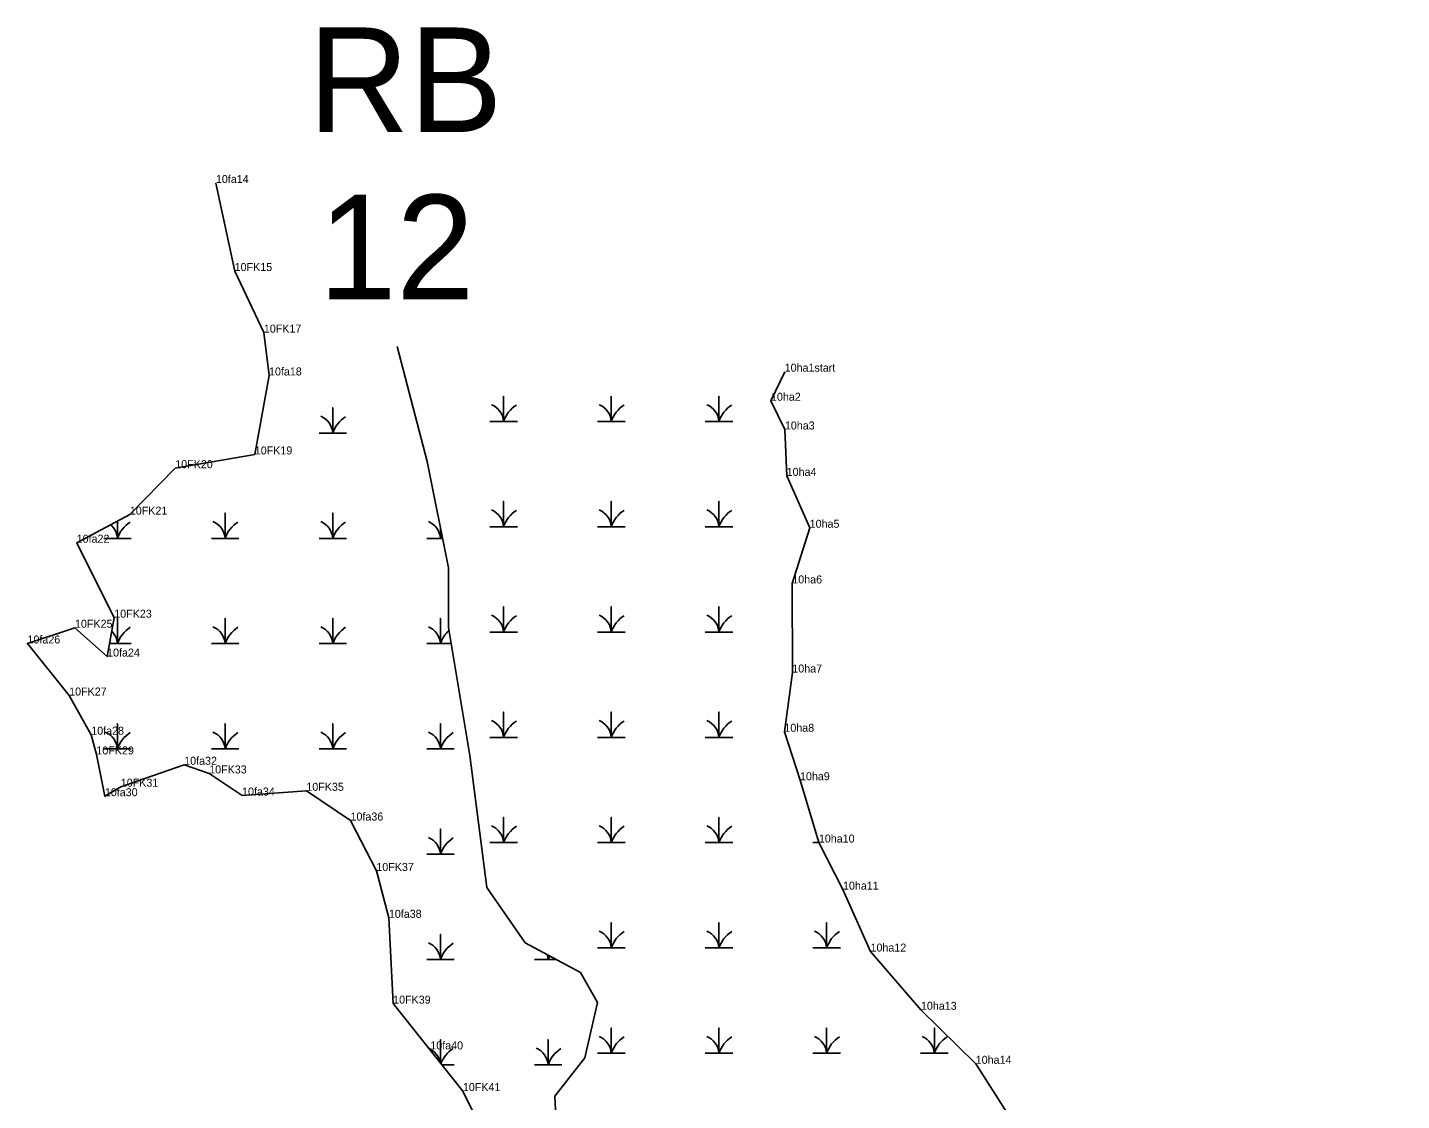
# Model space of a CAD drawing. Extents: x 2072529 to 2268796, y 436423 to 470397.
# Drawn here: x 2218305 to 2219163, y 449933 to 450603 of the extents above; entities that cross this region are included whole.
import ezdxf

# ---------------------------------------------------------------- set-up
doc = ezdxf.new("R2010")
doc.units = 0
for name, color, linetype in [('Default', 7, 'Continuous'), ('Exist Environmental Wetland Boundary', 7, 'Continuous'), ('Exist Environmental Wetland Boundary Cogo Comment', 7, 'Continuous'), ('Exist Environmental Wetland Boundary Cogo Point CELL', 7, 'Continuous'), ('Exist Hydro Jurisdictional Stream or Body of Water NEU Mitigable', 7, 'Continuous'), ('Exist Hydro Swamp or Marsh', 7, 'Continuous')]:
    doc.layers.add(name, color=color, linetype=linetype)

msp = doc.modelspace()

# ---------------------------------------------------------------- linework, layer by layer
at = {"layer": 'Exist Environmental Wetland Boundary'}
for points in [[(2218422.34, 450506.28), (2218434.05, 450451.3), (2218452.27, 450412.81), (2218455.5, 450386.02), (2218446.62, 450336.67), (2218396.94, 450328.09), (2218368.56, 450299.07), (2218335.38, 450281.52), (2218358.81, 450234.67), (2218354.37, 450210.38), (2218334.31, 450228.39), (2218304.63, 450218.55), (2218330.66, 450186.04), (2218344.46, 450161.54), (2218347.68, 450149.22), (2218352.97, 450123.12), (2218362.92, 450129.06), (2218402.51, 450142.76), (2218418.13, 450137.36), (2218438.68, 450123.54), (2218478.82, 450126.51), (2218506.4, 450107.92), (2218522.54, 450076.41), (2218530.37, 450047.14), (2218533.02, 449993.5), (2218576.58, 449938.89), (2218588.8, 449913.82)], [(2218777.6, 450388.4), (2218769.04, 450370.22), (2218777.71, 450352.27), (2218778.84, 450323.3), (2218793.2, 450290.87), (2218782.35, 450256.07), (2218782.37, 450200.42), (2218777.41, 450163.4), (2218787.16, 450133.1), (2218798.94, 450094.18), (2218814, 450064.74), (2218831.2, 450026.03), (2218862.69, 449989.66), (2218896.91, 449955.91), (2218918.55, 449921.84)]]:
    msp.add_lwpolyline(points, dxfattribs=at)
at = {"layer": 'Exist Environmental Wetland Boundary Cogo Point CELL'}
for p, q in [((2218422.34, 450506.28), (2218422.34, 450506.28)), ((2218434.05, 450451.3), (2218434.05, 450451.3)), ((2218434.05, 450451.3), (2218434.05, 450451.3)), ((2218452.27, 450412.81), (2218452.27, 450412.81)), ((2218452.27, 450412.81), (2218452.27, 450412.81)), ((2218455.5, 450386.02), (2218455.5, 450386.02)), ((2218777.6, 450388.4), (2218777.6, 450388.4)), ((2218769.04, 450370.22), (2218769.04, 450370.22)), ((2218769.04, 450370.22), (2218769.04, 450370.22)), ((2218777.71, 450352.27), (2218777.71, 450352.27)), ((2218446.62, 450336.67), (2218446.62, 450336.67)), ((2218446.62, 450336.67), (2218446.62, 450336.67)), ((2218396.94, 450328.09), (2218396.94, 450328.09)), ((2218396.94, 450328.09), (2218396.94, 450328.09)), ((2218778.84, 450323.3), (2218778.84, 450323.3)), ((2218778.84, 450323.3), (2218778.84, 450323.3)), ((2218368.56, 450299.07), (2218368.56, 450299.07)), ((2218368.56, 450299.07), (2218368.56, 450299.07)), ((2218793.2, 450290.87), (2218793.2, 450290.87)), ((2218335.38, 450281.52), (2218335.38, 450281.52)), ((2218782.35, 450256.07), (2218782.35, 450256.07)), ((2218782.35, 450256.07), (2218782.35, 450256.07)), ((2218358.81, 450234.67), (2218358.81, 450234.67)), ((2218358.81, 450234.67), (2218358.81, 450234.67)), ((2218334.31, 450228.39), (2218334.31, 450228.39)), ((2218334.31, 450228.39), (2218334.31, 450228.39)), ((2218304.63, 450218.55), (2218304.63, 450218.55)), ((2218354.37, 450210.38), (2218354.37, 450210.38)), ((2218782.37, 450200.42), (2218782.37, 450200.42)), ((2218330.66, 450186.04), (2218330.66, 450186.04)), ((2218330.66, 450186.04), (2218330.66, 450186.04)), ((2218344.46, 450161.54), (2218344.46, 450161.54)), ((2218777.41, 450163.4), (2218777.41, 450163.4)), ((2218777.41, 450163.4), (2218777.41, 450163.4)), ((2218347.68, 450149.22), (2218347.68, 450149.22)), ((2218347.68, 450149.22), (2218347.68, 450149.22)), ((2218402.51, 450142.76), (2218402.51, 450142.76)), ((2218418.13, 450137.36), (2218418.13, 450137.36)), ((2218418.13, 450137.36), (2218418.13, 450137.36)), ((2218362.92, 450129.06), (2218362.92, 450129.06)), ((2218362.92, 450129.06), (2218362.92, 450129.06)), ((2218478.82, 450126.51), (2218478.82, 450126.51)), ((2218478.82, 450126.51), (2218478.82, 450126.51)), ((2218787.16, 450133.1), (2218787.16, 450133.1)), ((2218352.97, 450123.12), (2218352.97, 450123.12)), ((2218438.68, 450123.54), (2218438.68, 450123.54)), ((2218506.4, 450107.92), (2218506.4, 450107.92)), ((2218798.94, 450094.18), (2218798.94, 450094.18)), ((2218798.94, 450094.18), (2218798.94, 450094.18)), ((2218522.54, 450076.41), (2218522.54, 450076.41)), ((2218522.54, 450076.41), (2218522.54, 450076.41)), ((2218814, 450064.74), (2218814, 450064.74)), ((2218530.37, 450047.14), (2218530.37, 450047.14)), ((2218831.2, 450026.03), (2218831.2, 450026.03)), ((2218831.2, 450026.03), (2218831.2, 450026.03)), ((2218533.02, 449993.5), (2218533.02, 449993.5)), ((2218533.02, 449993.5), (2218533.02, 449993.5)), ((2218862.69, 449989.66), (2218862.69, 449989.66)), ((2218556.25, 449964.92), (2218556.25, 449964.92)), ((2218896.91, 449955.91), (2218896.91, 449955.91)), ((2218896.91, 449955.91), (2218896.91, 449955.91)), ((2218576.58, 449938.89), (2218576.58, 449938.89)), ((2218576.58, 449938.89), (2218576.58, 449938.89))]:
    msp.add_line(p, q, dxfattribs=at)
at = {"layer": 'Exist Hydro Jurisdictional Stream or Body of Water NEU Mitigable'}
msp.add_lwpolyline([(2218535.63, 450404.2), (2218554.25, 450332.33), (2218567.55, 450265.78), (2218567.55, 450228.51), (2218580.85, 450148.65), (2218591.49, 450066.12), (2218615.44, 450031.52), (2218650.02, 450012.88), (2218660.66, 449994.25), (2218652.68, 449959.64), (2218634.06, 449935.68), (2218636.72, 449879.78), (2218647.36, 449829.2), (2218711.2, 449786.61), (2218727.16, 449736.03), (2218769.73, 449597.6), (2218825.59, 449536.38), (2218892.1, 449475.15), (2218953.28, 449435.22), (2219051.71, 449381.98), (2219115.55, 449339.39), (2219162.87, 449300.4)], dxfattribs=at)
at = {"layer": 'Exist Hydro Swamp or Marsh'}
for points in [[(2218593.46, 450357.3), (2218602.06, 450357.3), (2218602.06, 450373.08), (2218602.06, 450357.3), (2218610.66, 450357.3)], [(2218660.71, 450357.3), (2218669.31, 450357.3), (2218669.31, 450373.08), (2218669.31, 450357.3), (2218677.91, 450357.3)], [(2218727.96, 450357.3), (2218736.56, 450357.3), (2218736.56, 450373.08), (2218736.56, 450357.3), (2218745.16, 450357.3)], [(2218486.73, 450350.05), (2218495.33, 450350.05), (2218495.33, 450365.83), (2218495.33, 450350.05), (2218503.93, 450350.05)], [(2218593.46, 450291.5), (2218602.06, 450291.5), (2218602.06, 450307.28), (2218602.06, 450291.5), (2218610.66, 450291.5)], [(2218660.71, 450291.5), (2218669.31, 450291.5), (2218669.31, 450307.28), (2218669.31, 450291.5), (2218677.91, 450291.5)], [(2218727.96, 450291.5), (2218736.56, 450291.5), (2218736.56, 450307.28), (2218736.56, 450291.5), (2218745.16, 450291.5)], [(2218419.48, 450284.25), (2218428.08, 450284.25), (2218428.08, 450300.03), (2218428.08, 450284.25), (2218436.68, 450284.25)], [(2218486.73, 450284.25), (2218495.33, 450284.25), (2218495.33, 450300.03), (2218495.33, 450284.25), (2218503.93, 450284.25)], [(2218352.23, 450284.25), (2218360.83, 450284.25), (2218360.83, 450294.97)], [(2218360.83, 450294.97), (2218360.83, 450284.25), (2218369.43, 450284.25)], [(2218553.98, 450284.25), (2218562.58, 450284.25), (2218562.58, 450290.67)], [(2218562.58, 450290.67), (2218562.58, 450284.25), (2218563.86, 450284.25)], [(2218593.46, 450225.7), (2218602.06, 450225.7), (2218602.06, 450241.48), (2218602.06, 450225.7), (2218610.66, 450225.7)], [(2218660.71, 450225.7), (2218669.31, 450225.7), (2218669.31, 450241.48), (2218669.31, 450225.7), (2218677.91, 450225.7)], [(2218727.96, 450225.7), (2218736.56, 450225.7), (2218736.56, 450241.48), (2218736.56, 450225.7), (2218745.16, 450225.7)], [(2218355.85, 450218.45), (2218360.83, 450218.45), (2218360.83, 450234.23), (2218360.83, 450218.45), (2218369.43, 450218.45)], [(2218419.48, 450218.45), (2218428.08, 450218.45), (2218428.08, 450234.23), (2218428.08, 450218.45), (2218436.68, 450218.45)], [(2218486.73, 450218.45), (2218495.33, 450218.45), (2218495.33, 450234.23), (2218495.33, 450218.45), (2218503.93, 450218.45)], [(2218553.98, 450218.45), (2218562.58, 450218.45), (2218562.58, 450234.23), (2218562.58, 450218.45), (2218569.23, 450218.45)], [(2218593.46, 450159.9), (2218602.06, 450159.9), (2218602.06, 450175.68), (2218602.06, 450159.9), (2218610.66, 450159.9)], [(2218660.71, 450159.9), (2218669.31, 450159.9), (2218669.31, 450175.68), (2218669.31, 450159.9), (2218677.91, 450159.9)], [(2218727.96, 450159.9), (2218736.56, 450159.9), (2218736.56, 450175.68), (2218736.56, 450159.9), (2218745.16, 450159.9)], [(2218352.23, 450152.65), (2218360.83, 450152.65), (2218360.83, 450168.43), (2218360.83, 450152.65), (2218369.43, 450152.65)], [(2218419.48, 450152.65), (2218428.08, 450152.65), (2218428.08, 450168.43), (2218428.08, 450152.65), (2218436.68, 450152.65)], [(2218486.73, 450152.65), (2218495.33, 450152.65), (2218495.33, 450168.43), (2218495.33, 450152.65), (2218503.93, 450152.65)], [(2218553.98, 450152.65), (2218562.58, 450152.65), (2218562.58, 450168.43), (2218562.58, 450152.65), (2218571.18, 450152.65)], [(2218593.46, 450094.1), (2218602.06, 450094.1), (2218602.06, 450109.88), (2218602.06, 450094.1), (2218610.66, 450094.1)], [(2218660.71, 450094.1), (2218669.31, 450094.1), (2218669.31, 450109.88), (2218669.31, 450094.1), (2218677.91, 450094.1)], [(2218727.96, 450094.1), (2218736.56, 450094.1), (2218736.56, 450109.88), (2218736.56, 450094.1), (2218745.16, 450094.1)], [(2218553.98, 450086.85), (2218562.58, 450086.85), (2218562.58, 450102.63), (2218562.58, 450086.85), (2218571.18, 450086.85)], [(2218795.21, 450094.1), (2218798.98, 450094.1)], [(2218660.71, 450028.3), (2218669.31, 450028.3), (2218669.31, 450044.08), (2218669.31, 450028.3), (2218677.91, 450028.3)], [(2218727.96, 450028.3), (2218736.56, 450028.3), (2218736.56, 450044.08), (2218736.56, 450028.3), (2218745.16, 450028.3)], [(2218795.21, 450028.3), (2218803.81, 450028.3), (2218803.81, 450044.08), (2218803.81, 450028.3), (2218812.41, 450028.3)], [(2218553.98, 450021.05), (2218562.58, 450021.05), (2218562.58, 450036.83), (2218562.58, 450021.05), (2218571.18, 450021.05)], [(2218621.23, 450021.05), (2218629.83, 450021.05), (2218629.83, 450023.76)], [(2218629.83, 450023.76), (2218629.83, 450021.05), (2218634.86, 450021.05)], [(2218660.71, 449962.5), (2218669.31, 449962.5), (2218669.31, 449978.28), (2218669.31, 449962.5), (2218677.91, 449962.5)], [(2218727.96, 449962.5), (2218736.56, 449962.5), (2218736.56, 449978.28), (2218736.56, 449962.5), (2218745.16, 449962.5)], [(2218795.21, 449962.5), (2218803.81, 449962.5), (2218803.81, 449978.28), (2218803.81, 449962.5), (2218812.41, 449962.5)], [(2218862.46, 449962.5), (2218871.06, 449962.5), (2218871.06, 449978.28), (2218871.06, 449962.5), (2218879.66, 449962.5)], [(2218562.58, 449956.44), (2218562.58, 449971.03), (2218562.58, 449956.44)], [(2218621.23, 449955.25), (2218629.83, 449955.25), (2218629.83, 449971.03), (2218629.83, 449955.25), (2218638.43, 449955.25)], [(2218563.53, 449955.25), (2218571.18, 449955.25)]]:
    msp.add_lwpolyline(points, dxfattribs=at)
for centre, radius, start, end in [((2218589.79, 450356.41), 12.3, 4.14034, 67.53497), ((2218620.3, 450351.24), 19.22, 122.12745, 161.62219), ((2218657.04, 450356.41), 12.3, 4.14034, 67.53497), ((2218687.55, 450351.24), 19.22, 122.12745, 161.62219), ((2218724.29, 450356.41), 12.3, 4.14034, 67.53497), ((2218754.8, 450351.24), 19.22, 122.12745, 161.62219), ((2218483.06, 450349.16), 12.3, 4.14034, 67.53497), ((2218513.57, 450343.99), 19.22, 122.12745, 161.62219), ((2218589.79, 450290.61), 12.3, 4.14034, 67.53497), ((2218620.3, 450285.44), 19.22, 122.12745, 161.62219), ((2218657.04, 450290.61), 12.3, 4.14034, 67.53497), ((2218687.55, 450285.44), 19.22, 122.12745, 161.62219), ((2218724.29, 450290.61), 12.3, 4.14034, 67.53497), ((2218754.8, 450285.44), 19.22, 122.12745, 161.62219), ((2218348.56, 450283.36), 12.3, 4.14034, 49.48775), ((2218379.07, 450278.19), 19.22, 122.12745, 161.62219), ((2218415.81, 450283.36), 12.3, 4.14034, 67.53497), ((2218446.32, 450278.19), 19.22, 122.12745, 161.62219), ((2218483.06, 450283.36), 12.3, 4.14034, 67.53497), ((2218513.57, 450278.19), 19.22, 122.12745, 161.62219), ((2218550.31, 450283.36), 12.3, 4.14034, 67.53497), ((2218580.82, 450278.19), 19.22, 154.75438, 161.62219), ((2218589.79, 450224.81), 12.3, 4.14034, 67.53497), ((2218620.3, 450219.64), 19.22, 122.12745, 161.62219), ((2218657.04, 450224.81), 12.3, 4.14034, 67.53497), ((2218687.55, 450219.64), 19.22, 122.12745, 161.62219), ((2218724.29, 450224.81), 12.3, 4.14034, 67.53497), ((2218754.8, 450219.64), 19.22, 122.12745, 161.62219), ((2218348.56, 450217.56), 12.3, 4.14034, 44.92732), ((2218379.07, 450212.39), 19.22, 122.12745, 161.62219), ((2218415.81, 450217.56), 12.3, 4.14034, 67.53497), ((2218446.32, 450212.39), 19.22, 122.12745, 161.62219), ((2218483.06, 450217.56), 12.3, 4.14034, 67.53497), ((2218513.57, 450212.39), 19.22, 122.12745, 161.62219), ((2218550.31, 450217.56), 12.3, 4.14034, 67.53497), ((2218580.82, 450212.39), 19.22, 132.34724, 161.62219), ((2218589.79, 450159.01), 12.3, 4.14034, 67.53497), ((2218620.3, 450153.84), 19.22, 122.12745, 161.62219), ((2218657.04, 450159.01), 12.3, 4.14034, 67.53497), ((2218687.55, 450153.84), 19.22, 122.12745, 161.62219), ((2218724.29, 450159.01), 12.3, 4.14034, 67.53497), ((2218754.8, 450153.84), 19.22, 122.12745, 161.62219), ((2218348.56, 450151.76), 12.3, 4.14034, 67.53497), ((2218379.07, 450146.59), 19.22, 122.12745, 161.62219), ((2218415.81, 450151.76), 12.3, 4.14034, 67.53497), ((2218446.32, 450146.59), 19.22, 122.12745, 161.62219), ((2218483.06, 450151.76), 12.3, 4.14034, 67.53497), ((2218513.57, 450146.59), 19.22, 122.12745, 161.62219), ((2218550.31, 450151.76), 12.3, 4.14034, 67.53497), ((2218580.82, 450146.59), 19.22, 122.12745, 161.62219), ((2218589.79, 450093.21), 12.3, 4.14034, 67.53497), ((2218620.3, 450088.04), 19.22, 122.12745, 161.62219), ((2218657.04, 450093.21), 12.3, 4.14034, 67.53497), ((2218687.55, 450088.04), 19.22, 122.12745, 161.62219), ((2218724.29, 450093.21), 12.3, 4.14034, 67.53497), ((2218754.8, 450088.04), 19.22, 122.12745, 161.62219), ((2218550.31, 450085.96), 12.3, 4.14034, 67.53497), ((2218580.82, 450080.79), 19.22, 122.12745, 161.62219), ((2218657.04, 450027.41), 12.3, 4.14034, 67.53497), ((2218687.55, 450022.24), 19.22, 122.12745, 161.62219), ((2218724.29, 450027.41), 12.3, 4.14034, 67.53497), ((2218754.8, 450022.24), 19.22, 122.12745, 161.62219), ((2218791.54, 450027.41), 12.3, 4.14034, 67.53497), ((2218822.05, 450022.24), 19.22, 122.12745, 161.62219), ((2218550.31, 450020.16), 12.3, 4.14034, 67.53497), ((2218580.82, 450014.99), 19.22, 122.12745, 161.62219), ((2218617.56, 450020.16), 12.3, 4.14034, 18.63762), ((2218648.07, 450014.99), 19.22, 154.45684, 161.62219), ((2218657.04, 449961.61), 12.3, 4.14034, 67.53497), ((2218687.55, 449956.44), 19.22, 122.12745, 161.62219), ((2218724.29, 449961.61), 12.3, 4.14034, 67.53497), ((2218754.8, 449956.44), 19.22, 122.12745, 161.62219), ((2218791.54, 449961.61), 12.3, 4.14034, 67.53497), ((2218822.05, 449956.44), 19.22, 122.12745, 161.62219), ((2218858.79, 449961.61), 12.3, 4.14034, 67.53497), ((2218889.3, 449956.44), 19.22, 122.12745, 161.62219), ((2218550.31, 449954.36), 12.3, 10.85034, 66.31481), ((2218580.82, 449949.19), 19.22, 122.12745, 159.01708), ((2218617.56, 449954.36), 12.3, 4.14034, 67.53497), ((2218648.07, 449949.19), 19.22, 122.12745, 161.62219)]:
    msp.add_arc(centre, radius, start, end, dxfattribs=at)

# ---------------------------------------------------------------- texts
at = {"layer": 'Default'}
for s, p in [('RB', (2218479.97, 450538.15)), ('12', (2218486.48, 450433.6))]:
    msp.add_text(s, height=65.34, dxfattribs=at).set_placement(p)
at = {"layer": 'Exist Environmental Wetland Boundary Cogo Comment'}
for s, p in [('10fa14', (2218422.34, 450506.28)), ('10FK15', (2218434.05, 450451.3)), ('10FK17', (2218452.27, 450412.81)), ('10ha1start', (2218777.6, 450388.4)), ('10fa18', (2218455.5, 450386.02)), ('10ha2', (2218769.04, 450370.22)), ('10ha3', (2218777.71, 450352.27)), ('10FK19', (2218446.62, 450336.67)), ('10FK20', (2218396.94, 450328.09)), ('10ha4', (2218778.84, 450323.3)), ('10FK21', (2218368.56, 450299.07)), ('10ha5', (2218793.2, 450290.87)), ('10fa22', (2218335.38, 450281.52)), ('10ha6', (2218782.35, 450256.07)), ('10FK23', (2218358.81, 450234.67)), ('10FK25', (2218334.31, 450228.39)), ('10fa26', (2218304.63, 450218.55)), ('10fa24', (2218354.37, 450210.38)), ('10ha7', (2218782.37, 450200.42)), ('10FK27', (2218330.66, 450186.04)), ('10fa28', (2218344.46, 450161.54)), ('10ha8', (2218777.41, 450163.4)), ('10FK29', (2218347.68, 450149.22)), ('10fa32', (2218402.51, 450142.76)), ('10FK33', (2218418.13, 450137.36)), ('10ha9', (2218787.16, 450133.1)), ('10fa30', (2218352.97, 450123.12)), ('10FK31', (2218362.92, 450129.06)), ('10fa34', (2218438.68, 450123.54)), ('10FK35', (2218478.82, 450126.51)), ('10fa36', (2218506.4, 450107.92)), ('10ha10', (2218798.94, 450094.18)), ('10FK37', (2218522.54, 450076.41)), ('10ha11', (2218814, 450064.74)), ('10fa38', (2218530.37, 450047.14)), ('10ha12', (2218831.2, 450026.03)), ('10FK39', (2218533.02, 449993.5)), ('10ha13', (2218862.69, 449989.66)), ('10fa40', (2218556.25, 449964.92)), ('10ha14', (2218896.91, 449955.91)), ('10FK41', (2218576.58, 449938.89))]:
    msp.add_text(s, height=5, dxfattribs=at).set_placement(p)

doc.saveas('drawing.dxf')
